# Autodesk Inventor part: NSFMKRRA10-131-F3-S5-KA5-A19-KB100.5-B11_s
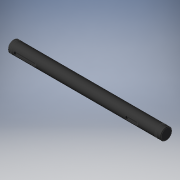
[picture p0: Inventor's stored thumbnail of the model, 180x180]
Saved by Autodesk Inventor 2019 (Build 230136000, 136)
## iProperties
Created: 2022-11
Part Number: NSFMKRRA10-131-F3-S5-KA5-A19-KB100.5-B11_s
Material: Generic
Catalog Web Link: www.cadenas.de
Description: NSFMKRR, SFMKRR, PSFMKRR, SSFMKRR, NSFHKRR, SFHKRR, PSFHKRR, SSFHKRR, NSFGKRR, SFGKRR, PSFGKRR, SSFGKRR, NSFMKRRA, SFMKRRA, PSFMKRRA, SSFMKRRA, NSFHKRRA, SFHKRR
Vendor: MISUMI
Document SubType Name: Modeling
Designer: psAdmin
Manufacturer: MISUMI
Mass: 10.1182 g
Surface Area: 43.8116 cm^2
Volume: 10.1182 cm^3
Density: 1 g/cm^3
Appearance: PSOLRGB-175-175-175
Category: PARTsolutions
Company: MISUMI
Title: NSFMKRRA10-131-F3-S5-KA5-A19-KB100.5-B11
Author: Cadenas PARTsolutions
Comments: Rotary Shafts - Retaining Ring Grooves on Both Ends with Keyway -
PSOL_IDENT_0: {$CADENAS_DATA/23d-libs/misumi/metric/11_rotary_shafts/11_components/psfgkrr/psfgkrr.prj},638 {VTYP=
PSOL_IDENT_1: 3D},{NB=NSFMKRRA10-131-F3-S5-KA5-A19-KB100.5-B11_s},{LINA=NSFMKRRA10-131-F3-S5-KA5-A19-KB100.5-B11},
PSOL_IDENT_2: {NN=NSFMKRR, SFMKRR, PSFMKRR, SSFMKRR, NSFHKRR, SFHKRR, PSFHKRR, SSFHKRR, NSFGKRR, SFGKRR, PSFGKRR,
PSOL_IDENT_3: SSFGKRR, NSFMKRRA, SFMKRRA, PSFMKRRA, SSFMKRRA, NSFHKRRA, SFHKRRA, PSFHKRRA, SSFHKRRA, NSFGKRRA, SFG
PSOL_IDENT_4: KRRA, PSFGKRRA, SSFGKRRA_shaft},{DATE=25.01.2022 23:09:52},{GEOMDATE=05.02.2021 08:15:17},{VERSION=}
PSOL_IDENT_5: ,{LINEID=30},{WBVAR=TS,TYS,MAT,ST,ALT1,L,F,S,NOK,KA,A,KB,B,KC,C,ALT3,FC,GALT3,WFC,J,WALT3,V,ALT4,SFC
PSOL_IDENT_6: ,SG,AG,ALT10,KWC,ALT11,WC,ALT5,UC,ALT7,SC,ALT32,CD},{WBNUMERIC=L,F,S,KA,A,KB,B,KC,C,FC,GALT3,WFC,J,W
PSOL_IDENT_7: ALT3,V,SFC,SG,AG,KWC,WC,UC,SC}  {NB=NSFMKRRA10-131-F3-S5-KA5-A19-KB100.5-B11_s},{LINA=NSFMKRRA10-131
PSOL_IDENT_8: -F3-S5-KA5-A19-KB100.5-B11},{KT=DUMMY},{PN=NSFMKRRA10-131-F3-S5-KA5-A19-KB100.5-B11},{TS=A},{TSALG=''
PSOL_IDENT_9: ,'Standard','A','Retaining Ring'},{TYS=M},{TYSALG= 'M','h9 (Cold-drawn)','H','h7 (Ground)','G','g6 (
PSOL_IDENT_10: Ground)' },{MAT=S45C},{MATALG= 'S45C','S45C Equivalent', 'SUS304','304 Stainless Steel' },{ST=},{STA
PSOL_IDENT_11: LG= '','-','BO','Black Oxide', 'ENP','Electroless Nickel Plating' },{TYPE=NSFMKRR},{D=10},{ALT1=},{L
PSOL_IDENT_12: KCMAX=799.9},{L=131.0},{LALG=[15:800/0.1]},{LMIN=15},{LMAX=800},{F=3.0},{FALG=[3:126/0.1]},{FMIN=3},
PSOL_IDENT_13: {FMAX1=122.8},{FMIN2=6.2},{FMAX2=126},{S=5.0},{SALG=[3:126/0.1]},{SMIN1=3},{SMAX1=121},{SMIN2=6.2},{
PSOL_IDENT_14: SMAX2=126},{DD=9.6},{MM=1.15},{MMALG=1.2},{MMJ=2},{NOK=2},{NOKALG= '1', 'with 1 Key Groove', '2'  , '
PSOL_IDENT_15: with 2 Key Grooves', '3'  , 'with 3 Key Grooves'},{CIFNOK1=0},{CIFNOK2=3},{CIFNOK3=0},{TOL1=0},{TOL2=
PSOL_IDENT_16: 3},{TOL3=0},{BB=3},{TT=1.8},{KA=5.0},{KAALG=[5:116/0.1]},{KAMIN1=0},{KAMIN2=5},{KAMIN3=129.2},{KAMAX
PSOL_IDENT_17: 1=-1000},{KAMAX2=116},{KAMAX3=-1000},{A=19.0},{AALG=[3:100/0.1]},{AMIN=3},{AMAX=100},{AMAX1=-1000},{
PSOL_IDENT_18: AMAX2=100},{AMAX3=-1000},{KAPN=-KA5-A19},{KB=100.5},{KBALG=[26:121/0.1]},{KBMIN1=26},{KBMIN2=26},{KB
PSOL_IDENT_19: MIN3=129.2},{KBMAX1=-1000},{KBMAX2=121},{KBMAX3=-1000},{B=11.0},{BALG=[3:23.5/0.1]},{BMIN=3},{BMAX=2
PSOL_IDENT_20: 3.5},{BMAX1=-1000},{BMAX2=23.5},{BMAX3=-1000},{KBPN=-KB100.5-B11},{KC=0.0},{KCALG=[0]},{KCMIN1=113.5
PSOL_IDENT_21: },{KCMIN2=113.5},{KCMIN3=129.2},{KCMAX1=-1000},{KCMAX2=-1000},{KCMAX3=-1000},{C=0.0},{CALG=0},{CMIN=
PSOL_IDENT_22: 3},{CMAX=-1000},{CMAX1=-1000},{CMAX2=-1000},{CMAX3=-1000},{CIFKA=5},{CIFKB=3},{CIFKC=3},{KCPN=},{ALT
PSOL_IDENT_23: 3=},{ALT3ALG= '', 'w/o Set Screw Flat','FC','with FC (Adds a Set Screw Flat)','WFC','with WFC (Adds
PSOL_IDENT_24: Two Set Screw Flats)','FCWFC','with FC + WFC (Adds Three Set Screw Flats)' },{ALT3PN=},{FC=0},{FCALG=
PSOL_IDENT_25: [0]},{FCMIN=0},{FCMAX=130},{GALT3=0},{GALT3ALG=[0]},{GALT3MIN=1},{GALT3MAX=70},{GALT3MAX2=70},{GALT3
PSOL_IDENT_26: MAX3=70},{WFC=0},{WFCALG=[0]},{WFCMIN=0},{WFCMIN2=2},{WFCMAX=127},{WFCMAX2=-3},{WFCMAX3=-4},{J=0},{J
PSOL_IDENT_27: ALG=[0]},{JMIN=1},{JMAX=70},{JMAX2=-2},{JMAX3=-5},{WALT3=0},{WALT3ALG=[0]},{WALT3MIN=0},{WALT3MIN2=1
PSOL_IDENT_28: 33},{WALT3MAX=128},{WALT3MAX2=128},{V=0},{VALG=[0]},{VMIN=1},{VMAX=70},{VMAX2=70},{CIFFC=0},{ALT4=},
PSOL_IDENT_29: {ALT4ALG= '', 'w/o SFC (2 Set Screw Flats (Angle Specified))', 'SFC'  , 'with SFC (2 Set Screw Flats
PSOL_IDENT_30: (Angle Specified))'},{ALT4PN=},{SFC=0},{SFCALG=[0]},{SFCMIN=0},{SFCMAX=130},{SG=0},{SGALG=[0]},{SGM
PSOL_IDENT_31: IN=1},{SGMAX=70},{AG=0},{AGALG=[0]},{H=0},{CIFSFC=0},{ALT10=},{ALT10ALG= '','Not applicable' },{KWC=
PSOL_IDENT_32: 0},{KWCALG=[0]},{KWCMIN=1},{KWCMAX=0},{WALT10=8},{ALT10PN=},{ALT11=},{ALT11ALG= '','Not applicable'
PSOL_IDENT_33: },{WC=0.0},{WCALG=[0]},{ALT11PN=},{ALT5=},{ALT5ALG= '', 'w/o UC (Slit Cam Groove)', 'UC', 'with UC (
PSOL_IDENT_34: Slit Cam Groove)'},{ALT5PN=},{UC=0},{UCALG=[0]},{UCMIN=1},{UCMAX=125},{DDALT5=0},{LL1=0},{ALT7=},{AL
PSOL_IDENT_35: T7ALG= '', 'w/o SC (Wrench Flats)', 'SC', 'with SC (Wrench Flats)'},{ALT7PN=},{SC=0},{SCALG=[0]},{SC
PSOL_IDENT_36: MIN=0},{SCMAX=123},{LL2=0},{LL2ALG=8},{WALT7=0},{CIFSC=0},{ALT32=},{ALT32ALG= '','w/o CD (Changes Pa
PSOL_IDENT_37: rt D Chamfering)','CD','with CD (Changes Part D Chamfering)' },{CD=},{CDALG= '','N/A' },{CD3D=0.5},{
PSOL_IDENT_38: ALT32PN=},{CIF323R=0},{CIF323L=0},{CIF324R=0},{CIF324L=0},{CIF3210=0},{CIF32F=0},{CIF32S=0},{ERRORPN=
PSOL_IDENT_39: },{ERRORKGALT3=OK},{ERRORKGALT4=OK},{ERRORKGALT5=OK},{ERRORKGALT7=OK},{ERRORKGALT10=OK},{ERRORRALT3=
PSOL_IDENT_40: OK},{ERRORRALT4=NG},{ERRORRALT5=NG},{ERRORRALT7=NG},{ERRORRALT10=OK},{ERRORALT34=OK},{ERRORALT35=OK}
PSOL_IDENT_41: ,{ERRORALT37=OK},{ERRORALT310=OK},{ERRORALT45=OK},{ERRORALT47=OK},{ERRORALT410=OK},{ERRORALT57=OK},{
PSOL_IDENT_42: ERRORALT510=OK},{ERRORALT710=OK},{PCUT3D=0},{QCUT3D=0},{TTALT2=1.8},{BBALT2=3}
NB: NSFMKRRA10-131-F3-S5-KA5-A19-KB100.5-B11_s
NN: NSFMKRR, SFMKRR, PSFMKRR, SSFMKRR, NSFHKRR, SFHKRR, PSFHKRR, SSFHKRR, NSFGKRR, SFGKRR, PSFGKRR, SSFGKRR, NSFMKRRA, SFMKRRA, PSFMKRRA, SSFMKRRA, NSFHKRRA, SFHKRR
NT: Rotary Shafts - Retaining Ring Grooves on Both Ends with Keyway -
NBSYN: $PN._s
LINA: NSFMKRRA10-131-F3-S5-KA5-A19-KB100.5-B11
CATALOG: Misumi
PN: NSFMKRRA10-131-F3-S5-KA5-A19-KB100.5-B11
TS: Retaining Ring
TYS: h9 (Cold-drawn)
MAT: S45C Equivalent
ST: -
D: 10
ALT1: w/o LKC (Changes L Tolerance)
L: 131
F: 3
S: 5
DD: 9.6
MM: 1.15
NOK: with 2 Key Grooves
KA: 5
A: 19
KB: 100.5
B: 11
KC: 0
C: 0
ALT3: w/o Set Screw Flat
FC: 0
GALT3: 0
WFC: 0
J: 0
WALT3: 0
V: 0
ALT4: w/o SFC (2 Set Screw Flats (Angle Specified))
SFC: 0
SG: 0
AG: 0
H: 0
ALT10: Not applicable
KWC: 0
ALT11: Not applicable
WC: 0
ALT5: w/o UC (Slit Cam Groove)
UC: 0
DDALT5: 0
LL1: 0
ALT7: w/o SC (Wrench Flats)
SC: 0
LL2: 0
WALT7: 0
ALT32: w/o CD (Changes Part D Chamfering)
CD: N/A
SUPPLIER: MISUMI
ARTICLENO: NSFMKRRA10-131-F3-S5-KA5-A19-KB100.5-B11_s
BOMINFO: NSFMKRRA10-131-F3-S5-KA5-A19-KB100.5-B11
CREATOR: CADENAS GmbH
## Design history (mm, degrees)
sketch "Sketch_1"
  geometry: L1 (-131, 0)-(0, 0); L2 (0, 0)-(0, -4.5); L3 (0, -4.5)-(-0.5, -5); L4 (-0.5, -5)-(-130.5, -5); L5 (-130.5, -5)-(-131, -4.5); L6 (-131, -4.5)-(-131, 0); L7 (-131, 0)-(0, 0)
  constraints: 14 end point
revolve "Revolution1" sketch "Sketch_1" stored, may be unused: angle "d0" = 360 deg
sketch "Sketch_27"
  geometry: L1 (131, 0)-(-131, 0); L2 (1.85, 9.6)-(1.85, 4.8); L3 (1.85, 4.8)-(3, 4.8); L4 (3, 4.8)-(3, 9.6); L5 (3, 9.6)-(1.85, 9.6)
  constraints: 10 end point
revolve "Revolution2" sketch "Sketch_27" stored, may be unused: angle "d1" = 360 deg
sketch "Sketch_39"
  geometry: L1 (131, 0)-(-131, 0); L2 (126, 9.6)-(126, 4.8); L3 (126, 4.8)-(127.15, 4.8); L4 (127.15, 4.8)-(127.15, 9.6); L5 (127.15, 9.6)-(126, 9.6)
  constraints: 10 end point
revolve "Revolution3" sketch "Sketch_39" stored, may be unused: angle "d2" = 360 deg
sketch "_____7"
  geometry: L1 (6.5, -1.5)-(22.5, -1.5); L2 (22.5, 1.5)-(6.5, 1.5); A1 r 1.5 centre (6.5, 0) between (6.5, 1.5) and (6.5, -1.5); A2 r 1.5 centre (22.5, 0) between (22.5, -1.5) and (22.5, 1.5)
  constraints: 4 end point, 4 point on circle, 2 centre point
extrude "Extrusion1" cut sketch "_____7" distance "d3" = 1.8; taper "d4" = 0 deg
sketch "_____10"
  geometry: L1 (102, -1.5)-(110, -1.5); L2 (110, 1.5)-(102, 1.5); A1 r 1.5 centre (102, 0) between (102, 1.5) and (102, -1.5); A2 r 1.5 centre (110, 0) between (110, -1.5) and (110, 1.5)
  constraints: 4 end point, 4 point on circle, 2 centre point
extrude "Extrusion2" cut sketch "_____10" distance "d5" = 1.8; taper "d6" = 0 deg
node "to_rring_1_XY"
node "to_rring_1_YZ"
node "to_rring_1_ZX"
node "to_rring_1_X"
node "to_rring_1_Y"
node "to_rring_1_Z"
node "to_rring_1_Center"
node "to_rring_2_XY"
node "to_rring_2_YZ"
node "to_rring_2_ZX"
node "to_rring_2_X"
node "to_rring_2_Y"
node "to_rring_2_Z"
node "to_rring_2_Center"
body "Solid1"
